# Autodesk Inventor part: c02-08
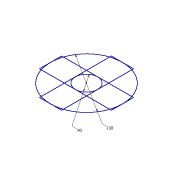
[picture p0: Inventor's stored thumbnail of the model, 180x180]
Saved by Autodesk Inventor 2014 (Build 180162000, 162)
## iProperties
Created: 2013-02
Part Number: c02-08
Material: Generic
Document SubType Name: Modeling
Designer: Thom Tremblay
Density: 1 g/cm^3
Appearance: Default
Author: Thom Tremblay
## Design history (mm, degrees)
sketch "Construction"
  geometry: L1 (-20, 65)-(20, 65); L2 (20, 65)-(20, -65); L3 (20, -65)-(-20, -65); L4 (-20, -65)-(-20, 65); L5 (-65, 20)-(65, 20); L6 (65, 20)-(65, -20); L7 (65, -20)-(-65, -20); L8 (-65, -20)-(-65, 20); C1 r 20 at (0, 0); C2 r 65 at (0, 0); 3 further points
  constraints: 16 end point, 8 tangent, 4 coincident, 4 parallel, 2 centre point, 2 horizontal, 2 perpendicular
  dimensions: "d8" = 40 diameter of C1; "d10" = 130 diameter of C2
sketch "Centerline"
  geometry: L1 (0, 0)-(80, 0); L2 (0, 17.993)-(80, 17.993); L3 (80, 17.993)-(80, 29.681); L4 (80, 29.681)-(34.583, 29.681); L5 (34.583, 29.681)-(20, 44.264); L6 (20, 44.264)-(0, 44.264); L7 (0, 32.628)-(3, 32.628); L8 (3, 32.628)-(3, 29.628); L9 (3, 29.628)-(0, 29.628); L10 (0, 44.264)-(0, 32.628); L11 (0, 29.628)-(0, 17.993)
  constraints: 22 end point, 6 perpendicular, 5 parallel, 2 collinear, 2 point on line, 1 horizontal
  dimensions: "d12" = 20 distance of L5.end L6.end; "d15" = 3 distance of L7.end L8.end; "d16" = 3 distance of L7.start L7.end; "d17" = 80 distance between parallel lines of L3 L10; "d18" = 45 deg angle of L5 L6
other parameters: "Thickness" = 0.5, "BendRadius" = 0.5 (= Thickness), "BendReliefWidth" = 0.5 (= Thickness), "BendReliefDepth" = 0.25 (= 0.5 x Thickness), "CornerReliefSize" = 2 (= 4 x Thickness), "SeamGap" = 0.01, "MinimumRemnant" = 1 (= 2 x Thickness), "TransitionRadius" = 0.5 (= BendRadius), "JacobiRadiusSize" = 0.5 (= BendRadius), "GapSize" = 0.5 (= Thickness)
